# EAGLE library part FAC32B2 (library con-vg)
CONNECTOR female, 32 pins, type C/2, rows AC, grid 5.08 mm
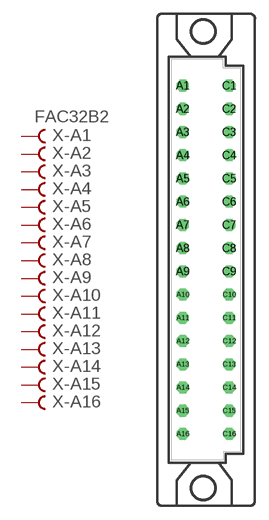
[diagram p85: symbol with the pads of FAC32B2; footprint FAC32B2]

Designator prefix X; gates -A1=FVAL -A2=FEM -A3=FEM -A4=FEM -A5=FEM -A6=FEM -A7=FEM -A8=FEM -A9=FEM -A10=FEM -A11=FEM -A12=FEM -A13=FEM -A14=FEM -A15=FEM -A16=FEM -C1=FVAL -C2=FEM -C3=FEM -C4=FEM -C5=FEM -C6=FEM -C7=FEM -C8=FEM -C9=FEM -C10=FEM -C11=FEM -C12=FEM -C13=FEM -C14=FEM -C15=FEM -C16=FEM

## FAC32B2  [FAC32B2]
A1  -A1:B  pas
A2  -A2:B  pas
A3  -A3:B  pas
A4  -A4:B  pas
A5  -A5:B  pas
A6  -A6:B  pas
A7  -A7:B  pas
A8  -A8:B  pas
A9  -A9:B  pas
A10  -A10:B  pas
A11  -A11:B  pas
A12  -A12:B  pas
A13  -A13:B  pas
A14  -A14:B  pas
A15  -A15:B  pas
A16  -A16:B  pas
C1  -C1:B  pas
C2  -C2:B  pas
C3  -C3:B  pas
C4  -C4:B  pas
C5  -C5:B  pas
C6  -C6:B  pas
C7  -C7:B  pas
C8  -C8:B  pas
C9  -C9:B  pas
C10  -C10:B  pas
C11  -C11:B  pas
C12  -C12:B  pas
C13  -C13:B  pas
C14  -C14:B  pas
C15  -C15:B  pas
C16  -C16:B  pas

## Footprint FAC32B2 (pad centres in mm)
CONNECTOR female, 32 pins, type C/2, rows AC, grid 5.08 mm
drill 0.813 octagon: A1 -1.27,19.05; A2 -1.27,16.51; A3 -1.27,13.97; A4 -1.27,11.43; A5 -1.27,8.89; A6 -1.27,6.35; A7 -1.27,3.81; A8 -1.27,1.27; A9 -1.27,-1.27; A10 -1.27,-3.81; A11 -1.27,-6.35; A12 -1.27,-8.89; A13 -1.27,-11.43; A14 -1.27,-13.97; A15 -1.27,-16.51; A16 -1.27,-19.05; C1 3.81,19.05; C2 3.81,16.51; C3 3.81,13.97; C4 3.81,11.43; C5 3.81,8.89; C6 3.81,6.35; C7 3.81,3.81; C8 3.81,1.27; C9 3.81,-1.27; C10 3.81,-3.81; C11 3.81,-6.35; C12 3.81,-8.89; C13 3.81,-11.43; C14 3.81,-13.97; C15 3.81,-16.51; C16 3.81,-19.05
hole 2.794 at 0.965,-25
hole 2.794 at 0.965,25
